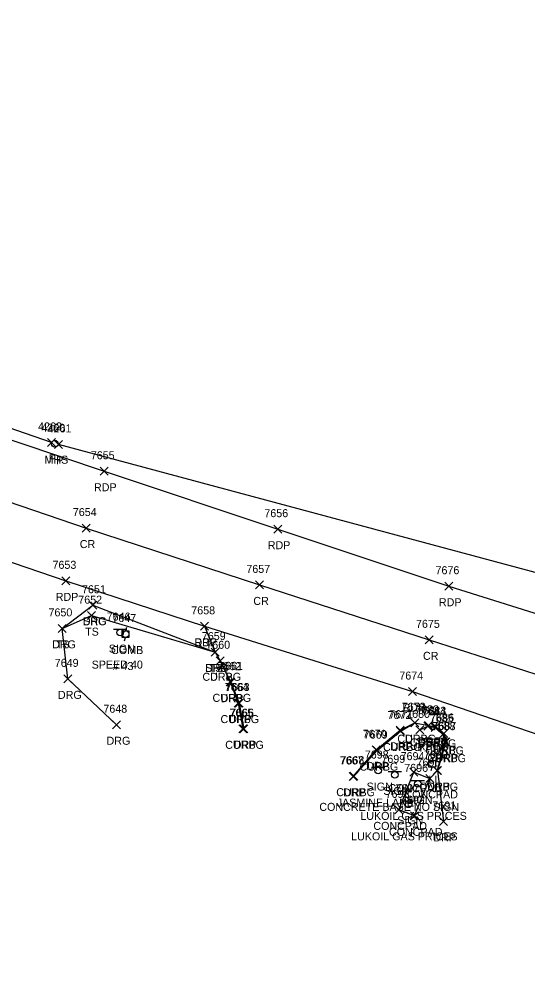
# Model space of a CAD drawing. Extents: x 1678863 to 1683592, y 407783 to 418211.
# Drawn here: x 1682107.2 to 1682234.2, y 417520.8 to 417762.3 of the extents above; entities that cross this region are included whole.
import ezdxf

# ---------------------------------------------------------------- set-up
doc = ezdxf.new("R2010")
doc.units = 0
for name, color, linetype in [('D_A', 7, 'Continuous'), ('D_I', 7, 'Continuous'), ('D_TIC', 7, 'Continuous'), ('DCP', 7, 'Continuous'), ('L_A', 7, 'Continuous'), ('L_I', 7, 'Continuous'), ('L_TIC', 7, 'Continuous'), ('LELB', 7, 'Continuous'), ('LS', 7, 'Continuous'), ('P_A', 7, 'Continuous'), ('P_I', 7, 'Continuous'), ('P_TIC', 7, 'Continuous'), ('PET', 7, 'Continuous'), ('PRC', 7, 'Continuous'), ('PSU', 7, 'Continuous'), ('R_A', 7, 'Continuous'), ('R_I', 7, 'Continuous'), ('R_TIC', 7, 'Continuous'), ('RC', 7, 'Continuous'), ('RDG', 7, 'Continuous'), ('RDP', 7, 'Continuous'), ('S_A', 7, 'Continuous'), ('S_C', 7, 'Continuous'), ('S_I', 7, 'Continuous'), ('SSGN', 7, 'Continuous'), ('U_A', 7, 'Continuous'), ('U_C', 7, 'Continuous'), ('U_I', 7, 'Continuous'), ('ULP', 7, 'Continuous'), ('UP', 7, 'Continuous'), ('USMH', 7, 'Continuous')]:
    doc.layers.add(name, color=color, linetype=linetype)

msp = doc.modelspace()

# ---------------------------------------------------------------- linework, layer by layer
at = {"layer": 'D_TIC'}
for points in [[(1682114.18, 417655.57), (1682116.18, 417657.57)], [(1682116.18, 417655.57), (1682114.18, 417657.57)], [(1682115.99, 417655.08), (1682117.99, 417657.08)], [(1682117.99, 417655.08), (1682115.99, 417657.08)]]:
    msp.add_lwpolyline(points, dxfattribs=at)
at = {"layer": 'DCP'}
for points in [[(1682115.18, 417656.57), (1681809.78, 417762.33)], [(1682480.47, 417558.38), (1682116.99, 417656.08)]]:
    msp.add_lwpolyline(points, dxfattribs=at)
at = {"layer": 'L_TIC'}
for points in [[(1682124.21, 417612.28), (1682126.21, 417614.28)], [(1682126.21, 417612.28), (1682124.21, 417614.28)], [(1682116.87, 417609.1), (1682118.87, 417611.1)], [(1682118.87, 417609.1), (1682116.87, 417611.1)], [(1682155.1, 417603.19), (1682157.1, 417605.19)], [(1682157.1, 417603.19), (1682155.1, 417605.19)], [(1682204.74, 417573.16), (1682206.74, 417575.16)], [(1682206.74, 417573.16), (1682204.74, 417575.16)], [(1682208.74, 417571.6), (1682210.74, 417573.6)], [(1682210.74, 417571.6), (1682208.74, 417573.6)], [(1682208.74, 417571.6), (1682210.74, 417573.6)], [(1682210.74, 417571.6), (1682208.74, 417573.6)], [(1682201, 417563.73), (1682203, 417565.73)], [(1682203, 417563.73), (1682201, 417565.73)], [(1682204.88, 417562.24), (1682206.88, 417564.24)], [(1682206.88, 417562.24), (1682204.88, 417564.24)], [(1682204.88, 417562.24), (1682206.88, 417564.24)], [(1682206.88, 417562.24), (1682204.88, 417564.24)]]:
    msp.add_lwpolyline(points, dxfattribs=at)
at = {"layer": 'LELB'}
msp.add_lwpolyline([(1682117.87, 417610.1), (1682125.21, 417613.28), (1682156.1, 417604.19)], dxfattribs=at)
at = {"layer": 'LS'}
for points in [[(1682205.88, 417563.24), (1682202, 417564.73), (1682205.74, 417574.16), (1682209.74, 417572.6)], [(1682205.88, 417563.24), (1682209.74, 417572.6)]]:
    msp.add_lwpolyline(points, dxfattribs=at)
at = {"layer": 'P_TIC'}
for points in [[(1682127.35, 417648.37), (1682129.35, 417650.37)], [(1682129.35, 417648.37), (1682127.35, 417650.37)], [(1682122.86, 417634.17), (1682124.86, 417636.17)], [(1682124.86, 417634.17), (1682122.86, 417636.17)], [(1682170.76, 417633.89), (1682172.76, 417635.89)], [(1682172.76, 417633.89), (1682170.76, 417635.89)], [(1682117.78, 417620.98), (1682119.78, 417622.98)], [(1682119.78, 417620.98), (1682117.78, 417622.98)], [(1682166.21, 417619.96), (1682168.21, 417621.96)], [(1682168.21, 417619.96), (1682166.21, 417621.96)], [(1682213.52, 417619.63), (1682215.52, 417621.63)], [(1682215.52, 417619.63), (1682213.52, 417621.63)], [(1682124.58, 417614.88), (1682126.58, 417616.88)], [(1682126.58, 417614.88), (1682124.58, 417616.88)], [(1682152.44, 417609.61), (1682154.44, 417611.61)], [(1682154.44, 417609.61), (1682152.44, 417611.61)], [(1682208.59, 417606.23), (1682210.59, 417608.23)], [(1682210.59, 417606.23), (1682208.59, 417608.23)], [(1682155.1, 417603.19), (1682157.1, 417605.19)], [(1682157.1, 417603.19), (1682155.1, 417605.19)], [(1682204.43, 417593.3), (1682206.43, 417595.3)], [(1682206.43, 417593.3), (1682204.43, 417595.3)]]:
    msp.add_lwpolyline(points, dxfattribs=at)
at = {"layer": 'PET'}
for points in [[(1681821.34, 417749.03), (1681866.77, 417735.42), (1681911.5, 417721.23), (1681955.33, 417706.25), (1681997.83, 417692.55), (1682042.13, 417677.99), (1682085.13, 417663.93), (1682128.35, 417649.37), (1682171.76, 417634.89), (1682214.52, 417620.63), (1682258.51, 417606.82), (1682302.78, 417595.62), (1682323.3, 417591.48), (1682345.13, 417586.22), (1682399.35, 417575.41), (1682449.39, 417567.95), (1682481.03, 417563.65)], [(1681812.45, 417721.17), (1681857.02, 417707.58), (1681903.16, 417692.98), (1681946.42, 417679.11), (1681968.39, 417670.98), (1682021.5, 417653.78), (1682032.55, 417650.27), (1682075.8, 417636.63), (1682118.78, 417621.98), (1682153.44, 417610.61), (1682205.43, 417594.3), (1682245.93, 417580.38), (1682292.99, 417565.78), (1682337.39, 417552.64), (1682388.21, 417539.97), (1682439.38, 417527.99), (1682479.06, 417520.79)]]:
    msp.add_lwpolyline(points, dxfattribs=at)
at = {"layer": 'PRC'}
msp.add_lwpolyline([(1681816.31, 417735.56), (1681861.69, 417721.85), (1681907.49, 417707.15), (1681950.48, 417692.95), (1681994.45, 417678.33), (1682037.13, 417663.93), (1682080.9, 417649.79), (1682123.86, 417635.17), (1682167.21, 417620.96), (1682209.59, 417607.23), (1682253.07, 417593.23), (1682297.24, 417579.39), (1682340.91, 417565.95), (1682392.16, 417553.08), (1682443.25, 417542.4), (1682480.44, 417535.79)], dxfattribs=at)
at = {"layer": 'PSU'}
msp.add_lwpolyline([(1682125.58, 417615.88), (1682156.1, 417604.19)], dxfattribs=at)
at = {"layer": 'R_TIC'}
for points in [[(1682124.58, 417614.88), (1682126.58, 417616.88)], [(1682126.58, 417614.88), (1682124.58, 417616.88)], [(1682116.87, 417609.1), (1682118.87, 417611.1)], [(1682118.87, 417609.1), (1682116.87, 417611.1)], [(1682152.44, 417609.61), (1682154.44, 417611.61)], [(1682154.44, 417609.61), (1682152.44, 417611.61)], [(1682155.1, 417603.19), (1682157.1, 417605.19)], [(1682157.1, 417603.19), (1682155.1, 417605.19)], [(1682156.34, 417601), (1682158.34, 417603)], [(1682158.34, 417601), (1682156.34, 417603)], [(1682156.34, 417601), (1682158.34, 417603)], [(1682158.34, 417601), (1682156.34, 417603)], [(1682118.34, 417596.48), (1682120.34, 417598.48)], [(1682120.34, 417596.48), (1682118.34, 417598.48)], [(1682158.87, 417595.73), (1682160.87, 417597.73)], [(1682160.87, 417595.73), (1682158.87, 417597.73)], [(1682158.99, 417595.65), (1682160.99, 417597.65)], [(1682160.99, 417595.65), (1682158.99, 417597.65)], [(1682160.86, 417590.42), (1682162.86, 417592.42)], [(1682162.86, 417590.42), (1682160.86, 417592.42)], [(1682161.12, 417590.44), (1682163.12, 417592.44)], [(1682163.12, 417590.44), (1682161.12, 417592.44)], [(1682130.48, 417585.01), (1682132.48, 417587.01)], [(1682132.48, 417585.01), (1682130.48, 417587.01)], [(1682205.03, 417585.52), (1682207.03, 417587.52)], [(1682207.03, 417585.52), (1682205.03, 417587.52)], [(1682205.03, 417585.52), (1682207.03, 417587.52)], [(1682207.03, 417585.52), (1682205.03, 417587.52)], [(1682208.24, 417584.62), (1682210.24, 417586.62)], [(1682210.24, 417584.62), (1682208.24, 417586.62)], [(1682208.37, 417584.86), (1682210.37, 417586.86)], [(1682210.37, 417584.86), (1682208.37, 417586.86)], [(1682162.03, 417583.99), (1682164.03, 417585.99)], [(1682164.03, 417583.99), (1682162.03, 417585.99)], [(1682162.25, 417584.02), (1682164.25, 417586.02)], [(1682164.25, 417584.02), (1682162.25, 417586.02)], [(1682201.33, 417583.64), (1682203.33, 417585.64)], [(1682203.33, 417583.64), (1682201.33, 417585.64)], [(1682201.45, 417583.44), (1682203.45, 417585.44)], [(1682203.45, 417583.44), (1682201.45, 417585.44)], [(1682206.23, 417583.73), (1682208.23, 417585.73)], [(1682208.23, 417583.73), (1682206.23, 417585.73)], [(1682210.11, 417584.36), (1682212.11, 417586.36)], [(1682212.11, 417584.36), (1682210.11, 417586.36)], [(1682210.2, 417584.5), (1682212.2, 417586.5)], [(1682212.2, 417584.5), (1682210.2, 417586.5)], [(1682212.02, 417582.59), (1682214.02, 417584.59)], [(1682214.02, 417582.59), (1682212.02, 417584.59)], [(1682212.21, 417582.82), (1682214.21, 417584.82)], [(1682214.21, 417582.82), (1682212.21, 417584.82)], [(1682212.51, 417580.65), (1682214.51, 417582.65)], [(1682214.51, 417580.65), (1682212.51, 417582.65)], [(1682212.7, 417580.73), (1682214.7, 417582.73)], [(1682214.7, 417580.73), (1682212.7, 417582.73)], [(1682195.37, 417578.74), (1682197.37, 417580.74)], [(1682197.37, 417578.74), (1682195.37, 417580.74)], [(1682195.6, 417578.54), (1682197.6, 417580.54)], [(1682197.6, 417578.54), (1682195.6, 417580.54)], [(1682210.54, 417573.54), (1682212.54, 417575.54)], [(1682212.54, 417573.54), (1682210.54, 417575.54)], [(1682210.66, 417573.57), (1682212.66, 417575.57)], [(1682212.66, 417573.57), (1682210.66, 417575.57)], [(1682189.6, 417572.08), (1682191.6, 417574.08)], [(1682191.6, 417572.08), (1682189.6, 417574.08)], [(1682189.78, 417572.15), (1682191.78, 417574.15)], [(1682191.78, 417572.15), (1682189.78, 417574.15)], [(1682212.12, 417560.84), (1682214.12, 417562.84)], [(1682214.12, 417560.84), (1682212.12, 417562.84)]]:
    msp.add_lwpolyline(points, dxfattribs=at)
at = {"layer": 'RC'}
for points in [[(1682157.34, 417602), (1682159.87, 417596.73), (1682161.86, 417591.42), (1682163.03, 417584.99)], [(1682190.78, 417573.15), (1682196.6, 417579.54), (1682202.45, 417584.44), (1682206.03, 417586.52)], [(1682207.23, 417584.73), (1682209.24, 417585.62), (1682211.11, 417585.36), (1682213.02, 417583.59), (1682213.51, 417581.65), (1682211.54, 417574.54)]]:
    msp.add_lwpolyline(points, dxfattribs=at)
at = {"layer": 'RDG'}
msp.add_lwpolyline([(1682131.48, 417586.01), (1682119.34, 417597.48), (1682117.87, 417610.1), (1682125.58, 417615.88)], dxfattribs=at)
at = {"layer": 'RDP'}
for points in [[(1682153.44, 417610.61), (1682156.1, 417604.19), (1682157.34, 417602), (1682159.99, 417596.65), (1682162.12, 417591.44), (1682163.25, 417585.02)], [(1682190.6, 417573.08), (1682196.37, 417579.74), (1682202.33, 417584.64), (1682206.03, 417586.52), (1682209.37, 417585.86), (1682211.2, 417585.5), (1682213.21, 417583.82), (1682213.7, 417581.73), (1682211.66, 417574.57), (1682213.12, 417561.84)]]:
    msp.add_lwpolyline(points, dxfattribs=at)
at = {"layer": 'SSGN'}
for p, q in [((1682130.75, 417609.89), (1682134.08, 417609.89)), ((1682132.39, 417609.06), (1682132.39, 417609.06)), ((1682195.17, 417575.4), (1682198.5, 417575.4)), ((1682196.82, 417574.57), (1682196.82, 417574.57)), ((1682199.33, 417574.33), (1682202.67, 417574.33)), ((1682200.98, 417573.5), (1682200.98, 417573.5)), ((1682205.08, 417572.08), (1682208.42, 417572.08)), ((1682206.73, 417571.25), (1682206.73, 417571.25)), ((1682202.8, 417566.97), (1682206.13, 417566.97)), ((1682204.44, 417566.13), (1682204.44, 417566.13))]:
    msp.add_line(p, q, dxfattribs=at)
for centre in [(1682132.39, 417609.06), (1682196.82, 417574.57), (1682200.98, 417573.5), (1682206.73, 417571.25), (1682204.44, 417566.13)]:
    msp.add_circle(centre, 0.833, dxfattribs=at)
at = {"layer": 'ULP'}
for p, q in [((1682209.45, 417575.41), (1682209.45, 417577.08)), ((1682209.45, 417577.08), (1682211.12, 417577.08)), ((1682210.45, 417577.91), (1682210.29, 417577.08)), ((1682211.12, 417577.08), (1682211.12, 417575.41)), ((1682211.12, 417575.41), (1682209.45, 417575.41)), ((1682210.04, 417574.58), (1682210.29, 417575.41)), ((1682210.29, 417576.24), (1682210.29, 417576.24))]:
    msp.add_line(p, q, dxfattribs=at)
at = {"layer": 'UP'}
for p, q in [((1682132.9, 417607.85), (1682132.9, 417609.52)), ((1682132.9, 417609.52), (1682134.57, 417609.52)), ((1682133.99, 417610.35), (1682133.74, 417609.52)), ((1682133.74, 417608.68), (1682133.74, 417608.68)), ((1682134.57, 417609.52), (1682134.57, 417607.85)), ((1682134.57, 417607.85), (1682132.9, 417607.85)), ((1682133.49, 417607.02), (1682133.74, 417607.85))]:
    msp.add_line(p, q, dxfattribs=at)
msp.add_circle((1682133.74, 417608.68), 0.833, dxfattribs=at)
at = {"layer": 'USMH'}
for p, q in [((1682116.05, 417656.25), (1682116.05, 417656.25)), ((1682116.89, 417656.25), (1682116.89, 417656.25))]:
    msp.add_line(p, q, dxfattribs=at)
msp.add_circle((1682116.05, 417656.25), 0.833, dxfattribs=at)

# ---------------------------------------------------------------- texts
at = {"layer": 'D_A'}
for p in [(1682114.56, 417651.57), (1682116.37, 417651.08)]:
    msp.add_text('P', height=2, dxfattribs=at).set_placement(p)
at = {"layer": 'D_I'}
for s, p in [('4262', (1682111.87, 417659.57)), ('4261', (1682114.25, 417659.08))]:
    msp.add_text(s, height=2, dxfattribs=at).set_placement(p)
at = {"layer": 'L_A'}
for s, p in [('TS', (1682123.62, 417608.28)), ('TS', (1682116.28, 417605.1)), ('TS', (1682154.51, 417599.19)), ('CONCPAD', (1682199.39, 417569.16)), ('CONCPAD', (1682203.39, 417567.6)), ('CONCPAD', (1682203.39, 417567.6)), ('CONCPAD', (1682195.64, 417559.73)), ('CONCPAD', (1682199.52, 417558.24)), ('CONCPAD', (1682199.52, 417558.24))]:
    msp.add_text(s, height=2, dxfattribs=at).set_placement(p)
at = {"layer": 'L_I'}
for s, p in [('7652', (1682121.91, 417616.28)), ('7650', (1682114.47, 417613.1)), ('7659', (1682152.78, 417607.19)), ('7694', (1682202.44, 417577.16)), ('7695', (1682206.43, 417575.6)), ('7695', (1682206.43, 417575.6)), ('7693', (1682198.69, 417567.73)), ('7692', (1682202.57, 417566.24)), ('7692', (1682202.57, 417566.24))]:
    msp.add_text(s, height=2, dxfattribs=at).set_placement(p)
at = {"layer": 'P_A'}
for s, p in [('RDP', (1682125.83, 417644.37)), ('CR', (1682122.29, 417630.17)), ('RDP', (1682169.25, 417629.89)), ('RDP', (1682116.27, 417616.98)), ('CR', (1682165.64, 417615.96)), ('RDP', (1682212.01, 417615.63)), ('SHG', (1682123.11, 417610.88)), ('RDP', (1682150.93, 417605.61)), ('CR', (1682208.02, 417602.23)), ('SHG', (1682153.63, 417599.19)), ('RDP', (1682202.92, 417589.3))]:
    msp.add_text(s, height=2, dxfattribs=at).set_placement(p)
at = {"layer": 'P_I'}
for s, p in [('7655', (1682125.04, 417652.37)), ('7654', (1682120.55, 417638.17)), ('7656', (1682168.4, 417637.89)), ('7653', (1682115.47, 417624.98)), ('7657', (1682163.9, 417623.96)), ('7676', (1682211.16, 417623.63)), ('7651', (1682122.84, 417618.88)), ('7658', (1682150.14, 417613.61)), ('7675', (1682206.28, 417610.23)), ('7659', (1682152.78, 417607.19)), ('7674', (1682202.12, 417597.3))]:
    msp.add_text(s, height=2, dxfattribs=at).set_placement(p)
at = {"layer": 'R_A'}
for s, p in [('DRG', (1682123.06, 417610.88)), ('DRG', (1682115.36, 417605.1)), ('DRP', (1682150.93, 417605.61)), ('DRP', (1682153.58, 417599.19)), ('CURBG', (1682152.93, 417597)), ('DRP', (1682154.83, 417597)), ('DRG', (1682116.83, 417592.48)), ('CURBG', (1682155.45, 417591.73)), ('DRP', (1682157.48, 417591.65)), ('CURBG', (1682157.44, 417586.42)), ('DRP', (1682159.6, 417586.44)), ('DRG', (1682128.97, 417581.01)), ('CURBG', (1682158.62, 417579.99)), ('DRP', (1682160.74, 417580.02)), ('CURBG', (1682201.62, 417581.52)), ('CURBG', (1682202.81, 417579.73)), ('DRP', (1682203.52, 417581.52)), ('CURBG', (1682204.82, 417580.62)), ('CURBG', (1682206.69, 417580.36)), ('DRP', (1682206.86, 417580.86)), ('DRP', (1682208.69, 417580.5)), ('CURBG', (1682198.04, 417579.44)), ('DRP', (1682199.81, 417579.64)), ('CURBG', (1682208.6, 417578.59)), ('DRP', (1682210.7, 417578.82)), ('CURBG', (1682209.1, 417576.65)), ('DRP', (1682211.19, 417576.73)), ('CURBG', (1682192.19, 417574.54)), ('DRP', (1682193.85, 417574.74)), ('CURBG', (1682186.36, 417568.15)), ('DRP', (1682188.08, 417568.08)), ('CURBG', (1682207.12, 417569.54)), ('DRP', (1682209.15, 417569.57)), ('DRP', (1682210.61, 417556.84))]:
    msp.add_text(s, height=2, dxfattribs=at).set_placement(p)
at = {"layer": 'R_I'}
for s, p in [('7651', (1682122.84, 417618.88)), ('7658', (1682150.14, 417613.61)), ('7650', (1682114.47, 417613.1)), ('7659', (1682152.78, 417607.19)), ('7660', (1682153.9, 417605)), ('7660', (1682153.9, 417605)), ('7649', (1682116.03, 417600.48)), ('7662', (1682156.63, 417599.65)), ('7661', (1682157.08, 417599.73)), ('7664', (1682158.5, 417594.42)), ('7663', (1682158.76, 417594.44)), ('7673', (1682202.73, 417589.52)), ('7673', (1682202.73, 417589.52)), ('7648', (1682128.18, 417589.01)), ('7665', (1682159.68, 417587.99)), ('7666', (1682159.84, 417588.02)), ('7672', (1682199.15, 417587.44)), ('7671', (1682199.59, 417587.64)), ('7680', (1682203.83, 417587.73)), ('7682', (1682206.06, 417588.86)), ('7681', (1682206.5, 417588.62)), ('7684', (1682207.8, 417588.36)), ('7683', (1682207.89, 417588.5)), ('7685', (1682209.71, 417586.59)), ('7686', (1682209.85, 417586.82)), ('7688', (1682210.21, 417584.65)), ('7687', (1682210.4, 417584.73)), ('7670', (1682192.97, 417582.74)), ('7669', (1682193.24, 417582.54)), ('7689', (1682208.22, 417577.54)), ('7690', (1682208.27, 417577.57)), ('7667', (1682187.24, 417576.08)), ('7668', (1682187.42, 417576.15)), ('7691', (1682210.38, 417564.84))]:
    msp.add_text(s, height=2, dxfattribs=at).set_placement(p)
at = {"layer": 'S_A'}
for p in [(1682129.53, 417604.04), (1682193.95, 417569.55), (1682198.12, 417568.48), (1682203.87, 417566.23), (1682201.58, 417561.11)]:
    msp.add_text('SIGN', height=2, dxfattribs=at).set_placement(p)
at = {"layer": 'S_C'}
for s, p in [('SPEED 40', (1682125.25, 417600.04)), ('JASMINE LANE', (1682186.48, 417565.55)), ('CONCRETE BASE NO SIGN', (1682182.13, 417564.48)), ('LUKOIL GAS PRICES', (1682192.37, 417562.23)), ('LUKOIL GAS PRICES', (1682190.08, 417557.11))]:
    msp.add_text(s, height=2, dxfattribs=at).set_placement(p)
at = {"layer": 'S_I'}
for s, p in [('7646', (1682129.01, 417612.04)), ('7698', (1682193.49, 417577.55)), ('7699', (1682197.64, 417576.48)), ('7696', (1682203.35, 417574.23)), ('7697', (1682201.12, 417569.11))]:
    msp.add_text(s, height=2, dxfattribs=at).set_placement(p)
at = {"layer": 'U_A'}
for s, p in [('MHS', (1682113.47, 417651.25)), ('COMB', (1682130.12, 417603.68)), ('LI', (1682209.39, 417571.24))]:
    msp.add_text(s, height=2, dxfattribs=at).set_placement(p)
at = {"layer": 'U_C'}
msp.add_text('# 43', height=2, dxfattribs=at).set_placement((1682130.48, 417599.68))
at = {"layer": 'U_I'}
for s, p in [('4260', (1682112.66, 417659.25)), ('7647', (1682130.43, 417611.68)), ('7700', (1682206.86, 417579.24))]:
    msp.add_text(s, height=2, dxfattribs=at).set_placement(p)

doc.saveas('drawing.dxf')
